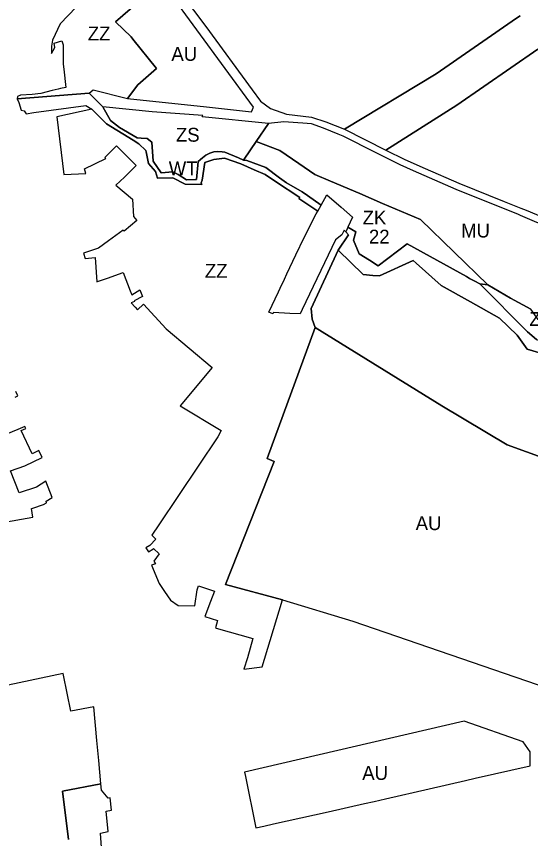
# Model space of a CAD drawing. Extents: x -522079 to -518833, y -1142398 to -1139961.
# Drawn here: x -520386 to -520015, y -1141332 to -1140739 of the extents above; entities that cross this region are included whole.
import ezdxf

# ---------------------------------------------------------------- set-up
doc = ezdxf.new("R2010")
doc.units = 0
for name, color, linetype in [('90640013', 7, 'Continuous'), ('90660013', 7, 'Continuous'), ('90670013', 7, 'Continuous'), ('90710013', 7, 'Continuous'), ('90710023', 7, 'Continuous'), ('90750013', 7, 'Continuous'), ('90830013', 7, 'Continuous'), ('ID_navrh', 7, 'Continuous')]:
    doc.layers.add(name, color=color, linetype=linetype)

msp = doc.modelspace()

# ---------------------------------------------------------------- linework, layer by layer
at = {"layer": '90640013'}
msp.add_lwpolyline([(-520333.88, -1140793.93), (-520385.85, -1140798.14), (-520384.61, -1140800.83), (-520383.09, -1140806.25), (-520380.85, -1140806.63), (-520379.43, -1140808.81), (-520373.88, -1140807.82), (-520336.41, -1140802.99), (-520331.98, -1140805.6), (-520332, -1140805.6), (-520321.54, -1140816.1), (-520302.1, -1140827.97), (-520298.02, -1140830.46), (-520293.05, -1140835.38), (-520292.87, -1140836.23), (-520291.11, -1140844.75), (-520286.12, -1140850.49), (-520284.67, -1140855.24), (-520273.49, -1140855.19), (-520264.75, -1140859.75), (-520252.57, -1140859.91), (-520253.04, -1140858.58), (-520252.48, -1140856.73), (-520250.57, -1140844.07), (-520243.98, -1140841.86), (-520236.26, -1140840.92), (-520224.47, -1140845.06), (-520214.8, -1140849.22), (-520206.95, -1140852.59), (-520199.46, -1140857.65), (-520181.95, -1140869.32), (-520182.55, -1140869.96), (-520168.95, -1140879.03), (-520167.79, -1140876.9), (-520166.62, -1140874.78), (-520176.48, -1140867.88), (-520180.27, -1140865.22), (-520191.59, -1140858.73), (-520196.46, -1140855.08), (-520206.43, -1140847.59), (-520220.12, -1140842.45), (-520222.55, -1140842.43), (-520226.15, -1140840.68), (-520236.14, -1140836.59), (-520237.99, -1140836.24), (-520241.55, -1140836.1), (-520243.86, -1140836.42), (-520246.91, -1140837.31), (-520249.76, -1140838.76), (-520252.14, -1140840.56), (-520255.19, -1140843.37), (-520256.4, -1140856.26), (-520263.6, -1140856.56), (-520269.7, -1140852.75), (-520273.45, -1140850.74), (-520282.03, -1140851.48), (-520287.73, -1140843.06), (-520288.8, -1140829.33), (-520292.1, -1140826.69), (-520296.51, -1140826.43), (-520299.28, -1140826.27), (-520312.05, -1140818.87), (-520318.65, -1140813.75), (-520323.97, -1140803.87)], close=True, dxfattribs=at)
msp.add_lwpolyline([(-520011.16, -1140971.75), (-520017.69, -1140966.19), (-520051.93, -1140931.48), (-520055.67, -1140929.56), (-520059.41, -1140927.64), (-520061.67, -1140926.36), (-520104.55, -1140902.75), (-520125.39, -1140918.45), (-520131.65, -1140914.52), (-520139.09, -1140909.85), (-520143.26, -1140900.05), (-520141.61, -1140894.1), (-520147.23, -1140890.72), (-520148.27, -1140892.97), (-520148.74, -1140894), (-520146.75, -1140896.12), (-520154.18, -1140907.23), (-520136.24, -1140924.81), (-520129.31, -1140925.55), (-520124.49, -1140925.8), (-520100.12, -1140914.78), (-520097.88, -1140916.76), (-520079.83, -1140932.73), (-520058.84, -1140944.58), (-520037.81, -1140956.24), (-520025.01, -1140968.52), (-520017.73, -1140978.78), (-520003.11, -1140982.94)], dxfattribs=at)
at = {"layer": '90660013'}
msp.add_lwpolyline([(-520213.5, -1140828.96), (-520204.62, -1140815.75), (-520252.34, -1140811), (-520251.92, -1140810), (-520288.38, -1140807.41), (-520323.97, -1140803.87), (-520318.65, -1140813.75), (-520312.05, -1140818.87), (-520299.28, -1140826.27), (-520296.51, -1140826.43), (-520292.1, -1140826.69), (-520288.8, -1140829.33), (-520287.73, -1140843.06), (-520282.03, -1140851.48), (-520273.45, -1140850.74), (-520269.7, -1140852.75), (-520263.6, -1140856.56), (-520256.4, -1140856.26), (-520255.19, -1140843.37), (-520252.14, -1140840.56), (-520249.76, -1140838.76), (-520246.91, -1140837.31), (-520243.86, -1140836.42), (-520241.55, -1140836.1), (-520237.99, -1140836.24), (-520236.14, -1140836.59), (-520226.15, -1140840.68), (-520222.55, -1140842.43), (-520217.49, -1140834.9)], close=True, dxfattribs=at)
at = {"layer": '90670013'}
for points in [[(-520320.58, -1140707.95), (-520354.98, -1140743.86), (-520360.42, -1140755.8), (-520361.11, -1140760.14), (-520361.04, -1140765.41), (-520358.59, -1140760.98), (-520359.31, -1140757.88), (-520353.64, -1140756.21), (-520352.78, -1140759.2), (-520352.71, -1140773.02), (-520352.17, -1140776.77), (-520350.89, -1140789.92), (-520354.62, -1140790.65), (-520356.2, -1140791.03), (-520360.72, -1140792.17), (-520368.73, -1140794.29), (-520374.96, -1140794.94), (-520383.53, -1140795.4), (-520385.62, -1140796.31), (-520385.85, -1140798.14), (-520333.88, -1140793.93), (-520331.09, -1140791.46), (-520306.3, -1140797.86), (-520298.77, -1140787.91), (-520285.25, -1140776.21), (-520302.54, -1140754.92), (-520303.74, -1140753.44), (-520314.83, -1140742.62), (-520298.98, -1140728.74)], [(-520387.31, -1141013.36), (-520385.38, -1141012.44), (-520386.94, -1141009.33)], [(-520397.79, -1141103.97), (-520374.68, -1141099.98), (-520375.66, -1141093.7), (-520374.62, -1141093.47), (-520366.94, -1141090.81), (-520364.74, -1141089.55), (-520364.98, -1141088.31), (-520360.71, -1141085.77), (-520365.3, -1141073.88), (-520371.97, -1141078.27), (-520384.48, -1141082.4), (-520390.79, -1141066.51), (-520380.42, -1141062.83), (-520367.77, -1141056.92), (-520370.31, -1141051.82), (-520375, -1141054.13), (-520382.96, -1141037.48), (-520379.56, -1141036.01), (-520380, -1141035.01), (-520380.26, -1141034.58), (-520385.48, -1141036.63), (-520399.24, -1141042.3)], [(-520324.17, -1141351.52), (-520325.53, -1141331.62), (-520325.78, -1141327.89), (-520320.3, -1141326.77), (-520321.67, -1141312.05), (-520317.9, -1141311.37), (-520318.74, -1141302.49), (-520320.11, -1141302.71), (-520325.09, -1141296.95), (-520325.5, -1141292.44), (-520353.1, -1141297.63), (-520348.74, -1141332.58)]]:
    msp.add_lwpolyline(points, dxfattribs=at)
msp.add_lwpolyline([(-520209, -1141207.86), (-520207.36, -1141202.47), (-520194.38, -1141159.65), (-520235.62, -1141148.58), (-520200.4, -1141059.73), (-520205.51, -1141057.7), (-520170.88, -1140963.13), (-520172.97, -1140956.99), (-520173.77, -1140949.3), (-520154.18, -1140907.23), (-520146.75, -1140896.12), (-520148.74, -1140894), (-520149.94, -1140892.73), (-520151.68, -1140896.26), (-520156.19, -1140899.86), (-520180.26, -1140950.09), (-520181.77, -1140953.24), (-520189.01, -1140952.86), (-520200.79, -1140952.24), (-520201.27, -1140953.32), (-520201.3, -1140953.32), (-520204.29, -1140951.99), (-520197.39, -1140937.44), (-520196.08, -1140934.67), (-520193, -1140928.16), (-520191.17, -1140924.29), (-520184.7, -1140910.65), (-520178.74, -1140898.05), (-520170.08, -1140881.1), (-520168.95, -1140879.03), (-520182.55, -1140869.96), (-520181.95, -1140869.32), (-520199.46, -1140857.65), (-520206.95, -1140852.59), (-520214.8, -1140849.22), (-520224.47, -1140845.06), (-520236.26, -1140840.92), (-520243.98, -1140841.86), (-520250.57, -1140844.07), (-520252.48, -1140856.73), (-520253.04, -1140858.58), (-520252.57, -1140859.91), (-520264.75, -1140859.75), (-520273.49, -1140855.19), (-520284.67, -1140855.24), (-520286.12, -1140850.49), (-520291.11, -1140844.75), (-520292.87, -1140836.23), (-520293.05, -1140835.38), (-520298.02, -1140830.46), (-520302.1, -1140827.97), (-520321.54, -1140816.1), (-520332, -1140805.6), (-520357.19, -1140810.98), (-520352.17, -1140852.78), (-520336.35, -1140852.04), (-520337.42, -1140848.62), (-520321.89, -1140841.23), (-520322.72, -1140840.41), (-520314.26, -1140831.9), (-520311.07, -1140835.07), (-520299.93, -1140846.14), (-520308.39, -1140854.65), (-520314.68, -1140860.36), (-520302.58, -1140870.36), (-520301.99, -1140882.96), (-520299.57, -1140885.75), (-520308.71, -1140893.63), (-520309.51, -1140892.73), (-520319.94, -1140900.63), (-520327.22, -1140905.73), (-520338.02, -1140909.41), (-520336.89, -1140913.16), (-520329.64, -1140912.5), (-520328.35, -1140930.16), (-520327.1, -1140929.75), (-520320.68, -1140927.43), (-520309.29, -1140923.33), (-520304.25, -1140936.55), (-520303.17, -1140939.4), (-520297.35, -1140935.94), (-520295.5, -1140940.8), (-520301.37, -1140943.86), (-520301.23, -1140944.23), (-520303.52, -1140945.28), (-520300.74, -1140948.36), (-520299.04, -1140950.24), (-520294.61, -1140946.2), (-520278.46, -1140964.1), (-520245.17, -1140991.88), (-520268.23, -1141019.69), (-520238.67, -1141037.33), (-520241.17, -1141042.05), (-520283.75, -1141105.56), (-520288.75, -1141112.92), (-520285.76, -1141115.8), (-520290.1, -1141120.29), (-520292.95, -1141121.95), (-520291.23, -1141124.89), (-520287.92, -1141122.9), (-520287.59, -1141122.55), (-520283.49, -1141126.48), (-520287.28, -1141131.69), (-520286.17, -1141133.59), (-520288.84, -1141134.57), (-520283.41, -1141147.79), (-520279.46, -1141153.62), (-520275.19, -1141159.91), (-520269.77, -1141163.56), (-520257.71, -1141163.82), (-520256.03, -1141152.27), (-520254.95, -1141149.39), (-520243.41, -1141153.37), (-520246.26, -1141160.66), (-520250.48, -1141171.53), (-520241.26, -1141174.54), (-520242.77, -1141179.78), (-520242.23, -1141179.94), (-520215.84, -1141187.57), (-520219.73, -1141201.41), (-520222.29, -1141209.66)], close=True, dxfattribs=at)
at = {"layer": '90710013'}
for points in [[(-520022.9, -1140738.15), (-520025.44, -1140739.97), (-520083.41, -1140780.15), (-520149.6, -1140820.02), (-520119.77, -1140834.99)], [(-520119.77, -1140834.99), (-520068.52, -1140802.68), (-520010.06, -1140762.16)]]:
    msp.add_lwpolyline(points, dxfattribs=at)
msp.add_lwpolyline([(-520015.17, -1140949.95), (-520029.76, -1140941.98), (-520046.33, -1140932.29), (-520051.93, -1140931.48), (-520017.69, -1140966.19), (-520011.16, -1140971.75), (-519979.37, -1140981.19), (-519965.47, -1140973.69), (-519974.08, -1140974.02), (-519986.94, -1140971.3), (-519999.3, -1140964.63), (-520002.28, -1140962.91), (-520009.84, -1140957.29)], close=True, dxfattribs=at)
at = {"layer": '90710023'}
msp.add_lwpolyline([(-520213.5, -1140828.96), (-520217.49, -1140834.9), (-520222.55, -1140842.43), (-520220.12, -1140842.45), (-520206.43, -1140847.59), (-520196.46, -1140855.08), (-520191.59, -1140858.73), (-520180.27, -1140865.22), (-520176.48, -1140867.88), (-520166.62, -1140874.78), (-520162.5, -1140867.24), (-520152.09, -1140876.15), (-520143.83, -1140883.35), (-520147.23, -1140890.72), (-520141.61, -1140894.1), (-520143.26, -1140900.05), (-520139.09, -1140909.85), (-520131.65, -1140914.52), (-520125.39, -1140918.45), (-520104.55, -1140902.75), (-520061.67, -1140926.36), (-520059.41, -1140927.64), (-520055.67, -1140929.56), (-520051.93, -1140931.48), (-520046.33, -1140932.29), (-520094.9, -1140885.23), (-520122.13, -1140873.55), (-520138.6, -1140866.49), (-520159.88, -1140857.36), (-520170.98, -1140852.6), (-520182.58, -1140844.72), (-520196.23, -1140835.45)], close=True, dxfattribs=at)
at = {"layer": '90750013'}
for points in [[(-520306.3, -1140797.86), (-520249.32, -1140803.75), (-520216.9, -1140807.42), (-520215.27, -1140803.99), (-520276.72, -1140720.19), (-520284.03, -1140723.41), (-520298.98, -1140728.74), (-520314.83, -1140742.62), (-520303.74, -1140753.44), (-520302.54, -1140754.92), (-520285.25, -1140776.21), (-520298.77, -1140787.91)], [(-520194.38, -1141159.65), (-520143.75, -1141175.06), (-520002.99, -1141223.35), (-519980.55, -1141165.39), (-519948.1, -1141084.44), (-519951.21, -1141077.01), (-520032.33, -1141047.7), (-520079.53, -1141019.58), (-520170.88, -1140963.13), (-520205.51, -1141057.7), (-520200.4, -1141059.73), (-520235.62, -1141148.58)], [(-520128.28, -1141304.98), (-520120.09, -1141303.14), (-520088.69, -1141295.96), (-520062.28, -1141289.92), (-520055.42, -1141288.36), (-520015.8, -1141279.3), (-520015.63, -1141269.2), (-520020.82, -1141261.97), (-520063.43, -1141247.22), (-520221.83, -1141283.92), (-520221.2, -1141287.03), (-520213.54, -1141324.07), (-520207.86, -1141322.8), (-520200.99, -1141321.26), (-520161.5, -1141312.42), (-520135.15, -1141306.52)]]:
    msp.add_lwpolyline(points, close=True, dxfattribs=at)
for points in [[(-520267.51, -1140722.14), (-520249.86, -1140745.99), (-520216.26, -1140791.5), (-520210.31, -1140799.64), (-520202.97, -1140805.12), (-520191.48, -1140809.25), (-520173.51, -1140811.18), (-520163.23, -1140814.61), (-520149.6, -1140820.02), (-520083.41, -1140780.15), (-520025.44, -1140739.97), (-520022.9, -1140738.15)], [(-520010.06, -1140762.16), (-520068.52, -1140802.68), (-520119.77, -1140834.99)], [(-520119.77, -1140834.99), (-520106.23, -1140841.79), (-520091.34, -1140848.28), (-520067.09, -1140858.86), (-520034.41, -1140872.06), (-520022.3, -1140876.95), (-520018.57, -1140878.52), (-519997.49, -1140887.4)], [(-520348.74, -1141332.58), (-520353.1, -1141297.63), (-520325.5, -1141292.44), (-520327.05, -1141275.53), (-520328.39, -1141261.02), (-520330.62, -1141236.74), (-520347.19, -1141239.81), (-520352.46, -1141213.96), (-520352.51, -1141213.97), (-520352.78, -1141212.63), (-520400.61, -1141222.82)]]:
    msp.add_lwpolyline(points, dxfattribs=at)
at = {"layer": '90830013'}
for points in [[(-519999.48, -1140892), (-520022.73, -1140882.19), (-520024.21, -1140881.57), (-520069.02, -1140863.47), (-520099.84, -1140850.03), (-520109.6, -1140845.72), (-520127.38, -1140836.75), (-520150.53, -1140825.07), (-520154.23, -1140823.56), (-520164.79, -1140819.27), (-520173.51, -1140816.17), (-520179.62, -1140815.67), (-520183.32, -1140815.4), (-520193.39, -1140814.61), (-520204.62, -1140815.75), (-520213.5, -1140828.96), (-520196.23, -1140835.45), (-520182.58, -1140844.72), (-520170.98, -1140852.6), (-520159.88, -1140857.36), (-520138.6, -1140866.49), (-520122.13, -1140873.55), (-520094.9, -1140885.23), (-520046.33, -1140932.29), (-520029.76, -1140941.98), (-520015.17, -1140949.95)], [(-520154.18, -1140907.23), (-520173.77, -1140949.3), (-520172.97, -1140956.99), (-520170.88, -1140963.13), (-520079.53, -1141019.58), (-520032.33, -1141047.7), (-519951.21, -1141077.01)], [(-520003.11, -1140982.94), (-520017.73, -1140978.78), (-520025.01, -1140968.52), (-520037.81, -1140956.24), (-520058.84, -1140944.58), (-520079.83, -1140932.73), (-520097.88, -1140916.76), (-520100.12, -1140914.78), (-520124.49, -1140925.8), (-520129.31, -1140925.55), (-520136.24, -1140924.81), (-520154.18, -1140907.23)]]:
    msp.add_lwpolyline(points, dxfattribs=at)

# ---------------------------------------------------------------- texts
at = {"layer": '90640013'}
msp.add_text('WT', height=10, rotation=0, dxfattribs=at).set_placement((-520276.52, -1140853.2))
at = {"layer": '90660013'}
msp.add_text('ZS', height=10, rotation=0, dxfattribs=at).set_placement((-520271.33, -1140829))
at = {"layer": '90670013'}
msp.add_text('ZZ', height=10, rotation=0, dxfattribs=at).set_placement((-520334.94, -1140755.96))
msp.add_text('ZZ', height=10, dxfattribs=at).set_placement((-520250.42, -1140927.14))
at = {"layer": '90710013'}
msp.add_text('ZK', height=10, rotation=0, dxfattribs=at).set_placement((-520016.34, -1140961.98))
at = {"layer": '90710023'}
msp.add_text('ZK', height=10, rotation=0, dxfattribs=at).set_placement((-520136.58, -1140888.74))
at = {"layer": '90750013'}
for p in [(-520274.59, -1140770.69), (-520098.3, -1141109.25), (-520136.86, -1141289.51)]:
    msp.add_text('AU', height=10, rotation=0, dxfattribs=at).set_placement(p)
at = {"layer": '90830013'}
msp.add_text('MU', height=10, rotation=0, dxfattribs=at).set_placement((-520065.5, -1140898.15))
at = {"layer": 'ID_navrh'}
msp.add_text('22', height=10, rotation=360, dxfattribs=at).set_placement((-520132.02, -1140902.5))

doc.saveas('drawing.dxf')
